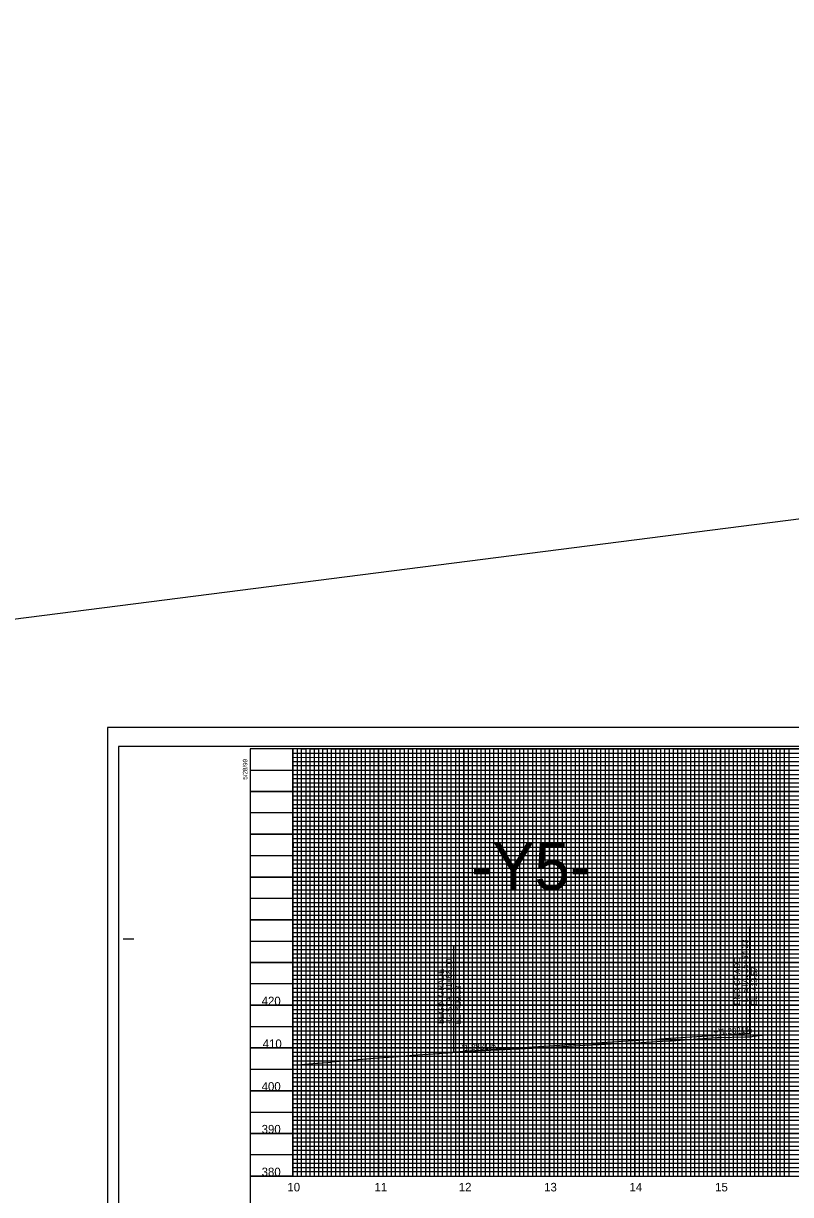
# Model space of a CAD drawing. Extents: x 571503 to 593215, y -77195 to -51828.
# Drawn here: x 587787 to 588685, y -53198 to -51828 of the extents above; entities that cross this region are included whole.
import ezdxf

# ---------------------------------------------------------------- set-up
doc = ezdxf.new("R2010")
doc.units = 0
for name, color, linetype in [('Default', 7, 'Continuous'), ('Exist Vertical Profile Ground Line', 7, 'Continuous'), ('Exist Vertical Profile Horizontal Axis Label Major', 7, 'Continuous'), ('Exist Vertical Profile Vertical Axis Label', 7, 'Continuous'), ('Prop PFL Text', 7, 'Continuous'), ('Prop Vertical Profile Grade', 7, 'Continuous'), ('Prop Vertical Profile Grade Label', 7, 'Continuous'), ('Prop VPI Label', 7, 'Continuous'), ('Sheet Clip Boundary CELL', 7, 'Continuous'), ('Sheet DOT Grid CELL', 7, 'Continuous'), ('Sheet Plot Border Inside CELL', 7, 'Continuous'), ('Sheet Plot Border Outside CELL', 7, 'Continuous'), ('Sheet Profile CELL', 7, 'Continuous'), ('Sheet Profile Grid Major CELL', 7, 'Continuous'), ('Sheet Profile Grid Middle CELL', 7, 'Continuous'), ('Sheet Profile Grid Minor CELL', 7, 'Continuous')]:
    doc.layers.add(name, color=color, linetype=linetype)

msp = doc.modelspace()

# ---------------------------------------------------------------- linework, layer by layer
at = {"layer": 'Default'}
msp.add_line((588102.5, -53176.9), (588052.5, -53176.9), dxfattribs=at)
at = {"layer": 'Exist Vertical Profile Ground Line'}
msp.add_lwpolyline([(588102.5, -53046.9), (588130.6, -53044.7), (588133.2, -53044.5), (588147, -53043.4), (588147.3, -53043.3), (588176.8, -53040.7), (588178.5, -53040.6), (588178.8, -53040.5), (588193.7, -53039.2), (588196.2, -53039), (588225.8, -53036.8), (588226, -53036.8), (588239.8, -53035.7), (588242.1, -53035.5), (588242.3, -53035.5), (588242.7, -53035.5), (588272.4, -53033.3), (588274.1, -53033.2), (588276.5, -53033), (588277.9, -53033), (588307.6, -53031.1), (588309.7, -53031), (588319.1, -53030.4), (588349.1, -53028.8), (588350.4, -53028.7), (588364.9, -53027.9), (588367, -53027.8), (588397, -53026.3), (588397.7, -53026.2), (588410.9, -53025.6), (588412.5, -53025.5), (588443, -53023.8), (588443.8, -53023.8), (588459.2, -53022.9), (588460.5, -53022.8), (588481.9, -53021.7), (588491.1, -53021.3), (588491.7, -53021.3), (588502.1, -53020.7), (588503.6, -53020.7), (588534.1, -53019), (588534.8, -53019), (588543.6, -53018.5), (588545.3, -53018.4), (588575.5, -53016.3), (588575.9, -53016.3), (588598.8, -53014.7), (588601, -53014.6), (588630.9, -53013.8), (588632.1, -53013.9), (588633.5, -53013.8), (588638.6, -53013.7), (588640.8, -53013), (588652.2, -53011.9), (588652.5, -53011.9), (588652.7, -53011.9), (588658.3, -53011.7)], dxfattribs=at)
at = {"layer": 'Prop PFL Text'}
msp.add_line((571799.6, -54572.4), (593215.4, -51828.4), dxfattribs=at)
at = {"layer": 'Prop Vertical Profile Grade'}
msp.add_line((588290.5, -53031.5), (588636.7, -53009.4), dxfattribs=at)
at = {"layer": 'Prop VPI Label'}
for p, q in [((588636.7, -53009.4), (588636.7, -52885.2)), ((588290.5, -53031.5), (588290.5, -52907.4))]:
    msp.add_line(p, q, dxfattribs=at)
at = {"layer": 'Sheet Clip Boundary CELL'}
msp.add_lwpolyline([(588102.5, -52676.9), (588102.5, -53176.9), (589502.5, -53176.9), (589502.5, -52814.5), (589352.4, -52814.5), (589352.4, -52676.9)], close=True, dxfattribs=at)
at = {"layer": 'Sheet DOT Grid CELL'}
for p, q in [((588102.5, -53176.9), (588102.5, -52676.9)), ((588102.5, -53176.9), (588102.5, -52676.9)), ((588152.5, -53176.9), (588152.5, -52676.9)), ((588152.5, -53176.9), (588152.5, -52676.9)), ((588202.5, -53176.9), (588202.5, -52676.9)), ((588202.5, -53176.9), (588202.5, -52676.9)), ((588252.5, -53176.9), (588252.5, -52676.9)), ((588252.5, -53176.9), (588252.5, -52676.9)), ((588302.5, -53176.9), (588302.5, -52676.9)), ((588302.5, -53176.9), (588302.5, -52676.9)), ((588352.5, -53176.9), (588352.5, -52676.9)), ((588352.5, -53176.9), (588352.5, -52676.9)), ((588402.5, -53176.9), (588402.5, -52676.9)), ((588402.5, -53176.9), (588402.5, -52676.9)), ((588452.5, -53176.9), (588452.5, -52676.9)), ((588452.5, -53176.9), (588452.5, -52676.9)), ((588502.5, -53176.9), (588502.5, -52676.9)), ((588502.5, -53176.9), (588502.5, -52676.9)), ((588552.5, -53176.9), (588552.5, -52676.9)), ((588552.5, -53176.9), (588552.5, -52676.9)), ((588602.5, -53176.9), (588602.5, -52676.9)), ((588602.5, -53176.9), (588602.5, -52676.9)), ((588652.5, -53176.9), (588652.5, -52676.9)), ((588652.5, -53176.9), (588652.5, -52676.9)), ((588052.5, -52726.9), (589352.4, -52726.9)), ((589352.4, -52726.9), (588052.5, -52726.9)), ((588052.5, -52776.9), (589352.4, -52776.9)), ((589352.4, -52776.9), (588052.5, -52776.9)), ((588052.5, -52826.9), (589552.5, -52826.9)), ((589552.5, -52826.9), (588052.5, -52826.9)), ((588052.5, -52876.9), (589552.5, -52876.9)), ((589552.5, -52876.9), (588052.5, -52876.9)), ((588052.5, -52926.9), (589552.5, -52926.9)), ((589552.5, -52926.9), (588052.5, -52926.9)), ((588052.5, -52976.9), (589552.5, -52976.9)), ((589552.5, -52976.9), (588052.5, -52976.9)), ((588052.5, -53026.9), (589552.5, -53026.9)), ((589552.5, -53026.9), (588052.5, -53026.9)), ((588052.5, -53076.9), (589552.5, -53076.9)), ((589552.5, -53076.9), (588052.5, -53076.9)), ((588052.5, -53126.9), (589552.5, -53126.9)), ((589552.5, -53126.9), (588052.5, -53126.9))]:
    msp.add_line(p, q, dxfattribs=at)
at = {"layer": 'Sheet Plot Border Inside CELL'}
msp.add_lwpolyline([(587898.5, -53729.5), (589565, -53729.5), (589565, -52674.4), (587898.5, -52674.4)], close=True, dxfattribs=at)
at = {"layer": 'Sheet Plot Border Outside CELL'}
msp.add_lwpolyline([(587885.5, -53751.9), (589569.5, -53751.9), (589569.5, -52651.9), (587885.5, -52651.9)], close=True, dxfattribs=at)
at = {"layer": 'Sheet Profile CELL'}
for p, q in [((589569.5, -52651.9), (587885.5, -52651.9)), ((587885.5, -52651.9), (587885.5, -53751.9)), ((587904, -52899.4), (587916.5, -52899.4)), ((588052.5, -53176.9), (589552.5, -53176.9))]:
    msp.add_line(p, q, dxfattribs=at)
msp.add_lwpolyline([(589552.5, -52676.9), (588052.5, -52676.9), (588052.5, -53726.9), (589552.5, -53726.9)], close=True, dxfattribs=at)
at = {"layer": 'Sheet Profile Grid Major CELL'}
for points in [[(588102.5, -52676.9), (588102.5, -53176.9), (588152.5, -53176.9), (588152.5, -52676.9), (588202.5, -52676.9), (588202.5, -53176.9), (588252.5, -53176.9), (588252.5, -52676.9), (588302.5, -52676.9), (588302.5, -53176.9), (588352.5, -53176.9), (588352.5, -52676.9), (588402.5, -52676.9), (588402.5, -53176.9), (588452.5, -53176.9), (588452.5, -52676.9), (588502.5, -52676.9), (588502.5, -53176.9), (588552.5, -53176.9), (588552.5, -52676.9), (588602.5, -52676.9), (588602.5, -53176.9), (588652.5, -53176.9), (588652.5, -52676.9), (588702.5, -52676.9)], [(588052.5, -52726.9), (589352.5, -52726.9)], [(589352.5, -52776.9), (588052.5, -52776.9), (588052.5, -52826.9), (589552.5, -52826.9)], [(589552.5, -52876.9), (588052.5, -52876.9), (588052.5, -52926.9), (589552.5, -52926.9)], [(589552.5, -52976.9), (588052.5, -52976.9), (588052.5, -53026.9), (589552.5, -53026.9)], [(589552.5, -53076.9), (588052.5, -53076.9), (588052.5, -53076.9), (588052.5, -53126.9), (589552.5, -53126.9)]]:
    msp.add_lwpolyline(points, dxfattribs=at)
at = {"layer": 'Sheet Profile Grid Middle CELL'}
msp.add_line((588052.5, -52701.9), (589352.4, -52701.9), dxfattribs=at)
for points in [[(588127.5, -52676.9), (588127.5, -53176.9), (588177.5, -53176.9), (588177.5, -52676.9), (588227.5, -52676.9), (588227.5, -53176.9), (588277.5, -53176.9), (588277.5, -52676.9), (588327.5, -52676.9), (588327.5, -53176.9), (588377.5, -53176.9), (588377.5, -52676.9), (588427.5, -52676.9), (588427.5, -53176.9), (588477.5, -53176.9), (588477.5, -52676.9), (588527.5, -52676.9), (588527.5, -53176.9), (588577.5, -53176.9), (588577.5, -52676.9), (588627.5, -52676.9), (588627.5, -53176.9), (588677.5, -53176.9), (588677.5, -53176.9), (588677.5, -52676.9), (588727.5, -52676.9)], [(589352.5, -52751.9), (588052.5, -52751.9), (588052.5, -52801.9), (589352.5, -52801.9)], [(589552.5, -52851.9), (588052.5, -52851.9), (588052.5, -52901.9), (589377.5, -52901.9)], [(589552.5, -52951.9), (588052.5, -52951.9), (588052.5, -53001.9), (589552.5, -53001.9)], [(589552.5, -53051.9), (588052.5, -53051.9), (588052.5, -53101.9), (589552.5, -53101.9)], [(589552.5, -53151.9), (588052.5, -53151.9)]]:
    msp.add_lwpolyline(points, dxfattribs=at)
at = {"layer": 'Sheet Profile Grid Minor CELL'}
for p, q in [((588102.5, -52681.9), (589352.5, -52681.9)), ((588102.5, -52686.9), (588102.5, -52686.9)), ((589352.5, -52686.9), (588102.5, -52687.3)), ((588102.5, -52691.9), (589352.5, -52691.9)), ((589352.4, -52811.9), (588102.5, -52811.9)), ((589502.5, -52816.9), (588102.5, -52816.9)), ((589502.5, -52821.9), (588102.5, -52821.9)), ((588102.5, -52831.9), (589502.5, -52831.9)), ((589502.5, -52836.9), (588102.5, -52836.9)), ((588102.5, -52841.9), (589502.5, -52841.9)), ((589502.5, -52861.9), (588102.5, -52861.9)), ((588102.5, -52866.9), (589502.5, -52866.9)), ((589502.5, -52886.9), (588102.5, -52886.9)), ((588102.5, -52891.9), (589502.5, -52891.9)), ((589502.5, -52911.9), (588102.5, -52911.9)), ((588102.5, -52916.9), (589502.5, -52916.9)), ((589502.5, -52921.9), (588102.5, -52921.9)), ((588102.5, -52931.9), (589502.5, -52931.9)), ((589502.5, -52936.9), (588102.5, -52936.9)), ((588102.5, -52941.9), (589502.5, -52941.9)), ((589502.5, -52946.9), (588102.5, -52946.9)), ((588102.5, -52956.9), (589502.5, -52956.9)), ((589502.5, -52961.9), (588102.5, -52961.9)), ((588102.5, -52966.9), (589502.5, -52966.9)), ((589502.5, -52971.9), (588102.5, -52971.9)), ((588102.5, -52981.9), (589502.5, -52981.9)), ((589502.5, -52986.9), (588102.5, -52986.9)), ((588102.5, -52991.9), (589502.5, -52991.9)), ((589502.5, -52996.9), (588102.5, -52996.9)), ((588102.5, -53006.9), (589502.5, -53006.9)), ((589502.5, -53011.9), (588102.5, -53011.9)), ((588102.5, -53016.9), (589502.5, -53016.9)), ((589502.5, -53021.9), (588102.5, -53021.9)), ((588102.5, -53031.9), (589502.5, -53031.9)), ((589502.5, -53036.9), (588102.5, -53036.9)), ((588102.5, -53041.9), (589502.5, -53041.9)), ((589502.5, -53046.9), (588102.5, -53046.9)), ((588102.5, -53056.9), (589502.5, -53056.9)), ((589502.5, -53061.9), (588102.5, -53061.9)), ((589502.5, -53066.9), (588102.5, -53066.9)), ((589502.5, -53071.9), (588102.5, -53071.9)), ((588102.5, -53081.9), (589502.5, -53081.9)), ((589502.5, -53086.9), (588102.5, -53086.9)), ((588102.5, -53091.9), (589502.5, -53091.9)), ((589502.5, -53096.9), (588102.5, -53096.9)), ((588102.5, -53106.9), (589502.5, -53106.9)), ((589502.5, -53111.9), (588102.5, -53111.9)), ((588102.5, -53116.9), (589502.5, -53116.9)), ((589502.5, -53121.9), (588102.5, -53121.9)), ((588102.5, -53131.9), (589502.5, -53131.9)), ((589502.5, -53136.9), (588102.5, -53136.9)), ((588102.5, -53141.9), (589502.5, -53141.9)), ((589502.5, -53146.9), (588102.5, -53146.9)), ((588102.5, -53156.9), (589502.5, -53156.9)), ((589502.5, -53161.9), (588102.5, -53161.9)), ((588102.5, -53166.9), (589502.5, -53166.9))]:
    msp.add_line(p, q, dxfattribs=at)
for points in [[(588107.5, -52676.9), (588107.5, -53176.9), (588112.5, -53176.9), (588112.5, -52676.9), (588117.5, -52676.9), (588117.5, -53176.9), (588122.5, -53176.9), (588122.5, -52676.9), (588132.5, -52676.9), (588132.5, -53176.9), (588137.5, -53176.9), (588137.5, -52676.9), (588142.5, -52676.9), (588142.5, -53176.9), (588147.5, -53176.9), (588157.5, -53176.9), (588162.5, -53176.9), (588162.5, -52676.9), (588167.5, -52676.9), (588167.5, -53176.9), (588172.5, -53176.9), (588172.5, -52676.9), (588182.5, -52676.9), (588182.5, -53176.9), (588187.5, -53176.9), (588187.5, -52676.9), (588192.5, -52676.9), (588192.5, -53176.9), (588197.5, -53176.9), (588197.5, -52676.9), (588207.5, -52676.9), (588207.5, -53176.9), (588212.5, -53176.9), (588212.5, -52676.9), (588217.5, -52676.9), (588217.5, -53176.9), (588222.5, -53176.9), (588222.5, -52676.9), (588232.5, -52676.9), (588232.5, -53176.9), (588237.5, -53176.9), (588237.5, -52676.9), (588242.5, -52676.9), (588242.5, -53176.9), (588247.5, -53176.9), (588247.5, -52676.9), (588257.5, -52676.9), (588257.5, -53176.9), (588262.5, -53176.9), (588262.5, -52676.9), (588267.5, -52676.9), (588267.5, -53176.9), (588272.5, -53176.9), (588272.5, -52676.9), (588282.5, -52676.9), (588282.5, -53176.9), (588287.5, -53176.9), (588287.5, -52676.9), (588292.5, -52676.9), (588292.5, -53176.9), (588297.5, -53176.9), (588297.5, -52676.9), (588307.5, -52676.9), (588307.5, -53176.9), (588312.5, -53176.9), (588312.5, -52676.9), (588317.5, -52676.9), (588317.5, -53176.9)], [(588147.5, -53176.9), (588147.5, -52676.9), (588157.5, -52676.9), (588157.5, -53176.9)], [(588317.5, -53176.9), (588322.5, -53176.9), (588322.5, -52676.9), (588332.5, -52676.9), (588332.5, -53176.9), (588337.5, -53176.9), (588337.5, -52676.9), (588342.5, -52676.9), (588342.5, -53176.9), (588347.5, -53176.9), (588347.5, -52676.9), (588357.5, -52676.9), (588357.5, -53176.9), (588362.5, -53176.9), (588362.5, -52676.9), (588367.5, -52676.9), (588367.5, -53176.9), (588372.5, -53176.9), (588372.5, -52676.9), (588382.5, -52676.9), (588382.5, -53176.9), (588387.5, -53176.9), (588387.5, -52676.9), (588392.5, -52676.9), (588392.5, -53176.9), (588397.5, -53176.9), (588397.5, -52676.9), (588407.5, -52676.9), (588407.5, -53176.9), (588412.5, -53176.9), (588412.5, -52676.9), (588417.5, -52676.9), (588417.5, -53176.9), (588422.5, -53176.9), (588422.5, -52676.9), (588432.5, -52676.9), (588432.5, -53176.9), (588437.5, -53176.9), (588437.5, -52676.9), (588442.5, -52676.9), (588442.5, -53176.9), (588447.5, -53176.9), (588447.5, -52676.9), (588457.5, -52676.9), (588457.5, -53176.9), (588462.5, -53176.9), (588462.5, -52676.9), (588467.5, -52676.9), (588467.5, -53176.9), (588472.5, -53176.9), (588472.5, -52676.9), (588482.5, -52676.9), (588482.5, -53176.9), (588487.5, -53176.9), (588487.5, -52676.9), (588492.5, -52676.9), (588492.5, -53176.9), (588497.5, -53176.9), (588497.5, -52676.9), (588507.5, -52676.9), (588507.5, -53176.9), (588512.5, -53176.9), (588512.5, -52676.9), (588517.5, -52676.9), (588517.5, -53176.9), (588522.5, -53176.9), (588522.5, -52676.9), (588532.5, -52676.9), (588532.5, -53176.9), (588537.5, -53176.9), (588537.5, -52676.9), (588542.5, -52676.9), (588542.5, -53176.9), (588547.5, -53176.9), (588547.5, -52676.9), (588557.5, -52676.9), (588557.5, -53176.9), (588562.5, -53176.9), (588562.5, -52676.9), (588567.5, -52676.9), (588567.5, -53176.9), (588572.5, -53176.9), (588572.5, -52676.9), (588582.5, -52676.9), (588582.5, -53176.9), (588587.5, -53176.9), (588587.5, -52676.9), (588592.5, -52676.9), (588592.5, -53176.9), (588597.5, -53176.9), (588597.5, -52676.9), (588607.5, -52676.9), (588607.5, -53176.9), (588612.5, -53176.9), (588612.5, -52676.9), (588617.5, -52676.9), (588617.5, -53176.9), (588622.5, -53176.9), (588622.5, -52676.9), (588632.5, -52676.9)], [(588632.5, -52676.9), (588632.5, -53176.9), (588637.5, -53176.9), (588637.5, -52676.9), (588642.5, -52676.9), (588642.5, -53176.9), (588647.5, -53176.9), (588647.5, -52676.9), (588657.5, -52676.9), (588657.5, -53176.9), (588662.5, -53176.9), (588662.5, -52676.9), (588667.5, -52676.9), (588667.5, -53176.9), (588672.5, -53176.9), (588672.5, -52676.9), (588682.5, -52676.9), (588682.5, -53176.9), (588687.5, -53176.9)], [(589352.5, -52696.9), (588102.5, -52696.9), (588102.5, -52706.9), (589352.5, -52706.9)], [(589352.4, -52711.9), (588102.5, -52711.9), (588102.5, -52716.9), (589352.5, -52716.9)], [(589352.5, -52721.9), (588102.5, -52721.9), (588102.5, -52731.9), (589352.5, -52731.9)], [(589352.5, -52736.9), (588102.5, -52736.9), (588102.5, -52741.9), (589352.5, -52741.9)], [(589352.5, -52746.9), (588102.5, -52746.9), (588102.5, -52756.9), (589352.5, -52756.9)], [(589352.5, -52761.9), (588102.5, -52761.9), (588102.5, -52766.9), (589352.5, -52766.9)], [(589352.5, -52771.9), (588102.5, -52771.9), (588102.5, -52781.9), (589352.5, -52781.9)], [(589352.5, -52796.9), (588102.5, -52796.9), (588102.5, -52806.9), (589352.5, -52806.9)], [(589352.5, -52787), (588102.6, -52787), (588102.6, -52791.9), (589352.5, -52791.9)], [(589502.5, -52846.9), (588102.5, -52846.9), (588102.5, -52856.9), (589502.5, -52856.9)], [(589502.5, -52871.9), (588102.5, -52871.9), (588102.5, -52881.9), (589502.5, -52881.9)], [(589502.5, -52896.9), (588102.5, -52896.9), (588102.5, -52906.9), (589502.5, -52906.9)], [(589502.5, -53171.9), (588102.5, -53171.9)]]:
    msp.add_lwpolyline(points, dxfattribs=at)

# ---------------------------------------------------------------- texts
at = {"layer": 'Default'}
msp.add_text('-Y5-', height=55.36, dxfattribs=at).set_placement((588311, -52842.1))
at = {"layer": 'Exist Vertical Profile Horizontal Axis Label Major'}
for s, p in [('10', (588096, -53194.7)), ('11', (588197.9, -53194.7)), ('12', (588296.4, -53194.7)), ('13', (588396.3, -53194.7)), ('14', (588496.1, -53194.7)), ('15', (588596.2, -53194.7))]:
    msp.add_text(s, height=10, dxfattribs=at).set_placement(p)
at = {"layer": 'Exist Vertical Profile Vertical Axis Label'}
for s, p in [('420', (588065.9, -52976.9)), ('410', (588067.1, -53026.9)), ('400', (588065.9, -53076.9)), ('390', (588065.9, -53126.9)), ('380', (588065.9, -53176.9))]:
    msp.add_text(s, height=10, dxfattribs=at).set_placement(p)
at = {"layer": 'Prop Vertical Profile Grade Label'}
for p in [(588591.4, -53012), (588291.4, -53030.8)]:
    msp.add_text('(+)1.2821%', height=7, rotation=3.668, dxfattribs=at).set_placement(p)
at = {"layer": 'Prop VPI Label'}
for s, p in [('-L- STA. 15+34.23', (588634.6, -52976.8)), ('-L- STA. 11+88.00', (588288.4, -52999)), ('END GRADE', (588625.3, -52976.8)), ('BEGIN GRADE', (588279.1, -52999)), ('EL. 413.57', (588645.4, -52977)), ('EL. 409.13', (588299.1, -52999.2))]:
    msp.add_text(s, height=7, rotation=90, dxfattribs=at).set_placement(p)
at = {"layer": 'Sheet Profile CELL'}
msp.add_text('5/28/99', height=5.25, rotation=90, dxfattribs=at).set_placement((588049.2, -52713))

doc.saveas('drawing.dxf')
